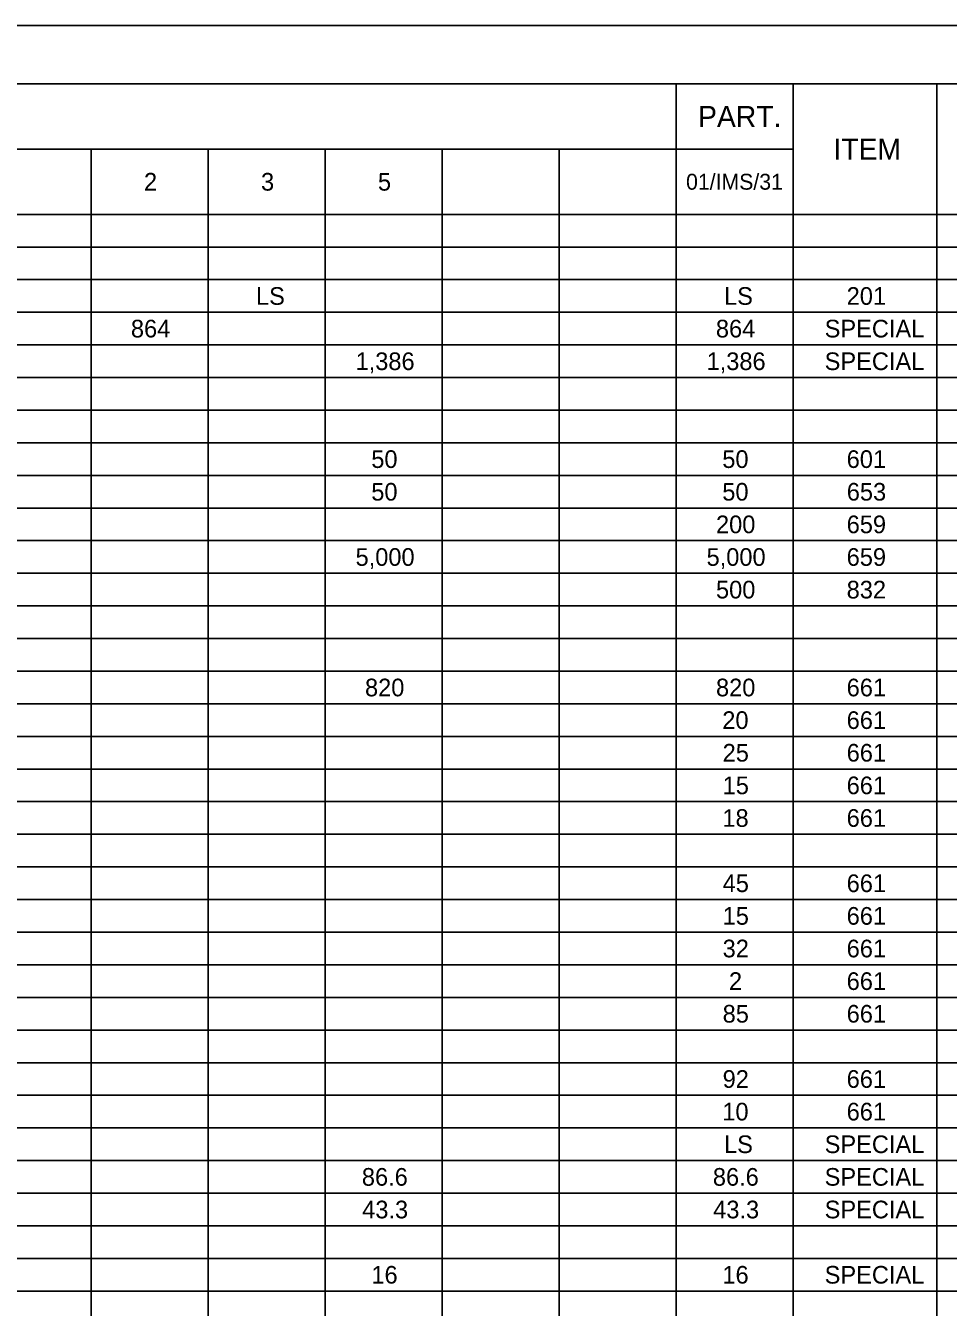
# Model space of a CAD drawing. Extents: x 0 to 34, y 0 to 22.
# Drawn here: x 8.98 to 16.9, y 11 to 22 of the extents above; entities that cross this region are included whole.
import ezdxf

# ---------------------------------------------------------------- set-up
doc = ezdxf.new("R2010")
doc.units = 0
for name, color, linetype in [('Default', 7, 'Continuous'), ('SH_Border', 7, 'Continuous'), ('SH_Cut_Line', 7, 'Continuous')]:
    doc.layers.add(name, color=color, linetype=linetype)

msp = doc.modelspace()

# ---------------------------------------------------------------- linework, layer by layer
at = {"layer": 'Default'}
for p, q in [((1.5, 21.5), (32.004, 21.5)), ((14.561, 21.5), (14.561, 0.5)), ((15.566, 21.5), (15.566, 0.5)), ((16.801, 21.5), (16.801, 0.5)), ((1.5, 20.94), (15.566, 20.94)), ((9.538, 20.94), (9.538, 0.5)), ((10.542, 20.94), (10.542, 0.5)), ((11.547, 20.94), (11.547, 0.5)), ((12.552, 20.94), (12.552, 0.5)), ((13.556, 20.94), (13.556, 0.5)), ((1.5, 20.38), (32.004, 20.38)), ((1.5, 20.1), (32.004, 20.1)), ((1.5, 19.82), (32.004, 19.82)), ((1.5, 19.54), (32.004, 19.54)), ((1.5, 19.26), (32.004, 19.26)), ((1.5, 18.98), (32.004, 18.98)), ((1.5, 18.7), (32.004, 18.7)), ((1.5, 18.42), (32.004, 18.42)), ((1.5, 18.14), (32.004, 18.14)), ((1.5, 17.86), (32.004, 17.86)), ((1.5, 17.58), (32.004, 17.58)), ((1.5, 17.3), (32.004, 17.3)), ((1.5, 17.02), (32.004, 17.02)), ((1.5, 16.74), (32.004, 16.74)), ((1.5, 16.46), (32.004, 16.46)), ((1.5, 16.18), (32.004, 16.18)), ((1.5, 15.9), (32.004, 15.9)), ((1.5, 15.62), (32.004, 15.62)), ((1.5, 15.34), (32.004, 15.34)), ((1.5, 15.06), (32.004, 15.06)), ((1.5, 14.78), (32.004, 14.78)), ((1.5, 14.5), (32.004, 14.5)), ((1.5, 14.22), (32.004, 14.22)), ((1.5, 13.94), (32.004, 13.94)), ((1.5, 13.66), (32.004, 13.66)), ((1.5, 13.38), (32.004, 13.38)), ((1.5, 13.1), (32.004, 13.1)), ((1.5, 12.82), (32.004, 12.82)), ((1.5, 12.54), (32.004, 12.54)), ((1.5, 12.26), (32.004, 12.26)), ((1.5, 11.98), (32.004, 11.98)), ((1.5, 11.7), (32.004, 11.7)), ((1.5, 11.42), (32.004, 11.42)), ((1.5, 11.14), (32.004, 11.14))]:
    msp.add_line(p, q, dxfattribs=at)
at = {"layer": 'SH_Border'}
msp.add_lwpolyline([(1.5, 21.5), (33.5, 21.5), (33.5, 0.5), (1.5, 0.5)], close=True, dxfattribs=at)
at = {"layer": 'SH_Cut_Line'}
msp.add_lwpolyline([(0, 0), (34, 0), (34, 22), (0, 22)], close=True, dxfattribs=at)

# ---------------------------------------------------------------- texts
at = {"layer": 'Default'}
for s, height, p in [('PART.', 0.1818, (14.75, 21.129)), ('ITEM', 0.1818, (15.912, 20.849)), ('2', 0.152, (9.992, 20.584)), ('3', 0.152, (10.997, 20.584)), ('5', 0.152, (12.001, 20.584)), ('01/IMS/31', 0.1364, (14.647, 20.592)), ('LS', 0.1515, (10.954, 19.604)), ('LS', 0.1515, (14.973, 19.604)), ('201', 0.1515, (16.026, 19.604)), ('864', 0.1515, (9.88, 19.324)), ('864', 0.1515, (14.903, 19.324)), ('SPECIAL', 0.1515, (15.837, 19.324)), ('1,386', 0.1515, (11.809, 19.044)), ('1,386', 0.1515, (14.823, 19.044)), ('SPECIAL', 0.1515, (15.837, 19.044)), ('50', 0.1515, (11.944, 18.204)), ('50', 0.1515, (14.958, 18.204)), ('601', 0.1515, (16.026, 18.204)), ('50', 0.1515, (11.944, 17.924)), ('50', 0.1515, (14.958, 17.924)), ('653', 0.1515, (16.027, 17.924)), ('200', 0.1515, (14.904, 17.644)), ('659', 0.1515, (16.026, 17.644)), ('5,000', 0.1515, (11.809, 17.364)), ('5,000', 0.1515, (14.823, 17.364)), ('659', 0.1515, (16.026, 17.364)), ('500', 0.1515, (14.904, 17.084)), ('832', 0.1515, (16.026, 17.084)), ('820', 0.1515, (11.89, 16.244)), ('820', 0.1515, (14.904, 16.244)), ('661', 0.1515, (16.026, 16.244)), ('20', 0.1515, (14.958, 15.964)), ('661', 0.1515, (16.026, 15.964)), ('25', 0.1515, (14.961, 15.684)), ('661', 0.1515, (16.026, 15.684)), ('15', 0.1515, (14.961, 15.404)), ('661', 0.1515, (16.026, 15.404)), ('18', 0.1515, (14.959, 15.124)), ('661', 0.1515, (16.026, 15.124)), ('45', 0.1515, (14.961, 14.564)), ('661', 0.1515, (16.026, 14.564)), ('15', 0.1515, (14.961, 14.284)), ('661', 0.1515, (16.026, 14.284)), ('32', 0.1515, (14.961, 14.004)), ('661', 0.1515, (16.026, 14.004)), ('2', 0.152, (15.015, 13.724)), ('661', 0.1515, (16.026, 13.724)), ('85', 0.1515, (14.961, 13.444)), ('661', 0.1515, (16.026, 13.444)), ('92', 0.1515, (14.961, 12.884)), ('661', 0.1515, (16.026, 12.884)), ('10', 0.1515, (14.958, 12.604)), ('661', 0.1515, (16.026, 12.604)), ('LS', 0.1515, (14.973, 12.324)), ('SPECIAL', 0.1515, (15.837, 12.324)), ('86.6', 0.1515, (11.863, 12.044)), ('86.6', 0.1515, (14.877, 12.044)), ('SPECIAL', 0.1515, (15.837, 12.044)), ('43.3', 0.1515, (11.866, 11.764)), ('43.3', 0.1515, (14.88, 11.764)), ('SPECIAL', 0.1515, (15.837, 11.764)), ('16', 0.1515, (11.945, 11.204)), ('16', 0.1515, (14.959, 11.204)), ('SPECIAL', 0.1515, (15.837, 11.204))]:
    msp.add_text(s, height=height, dxfattribs=at).set_placement(p)

doc.saveas('drawing.dxf')
